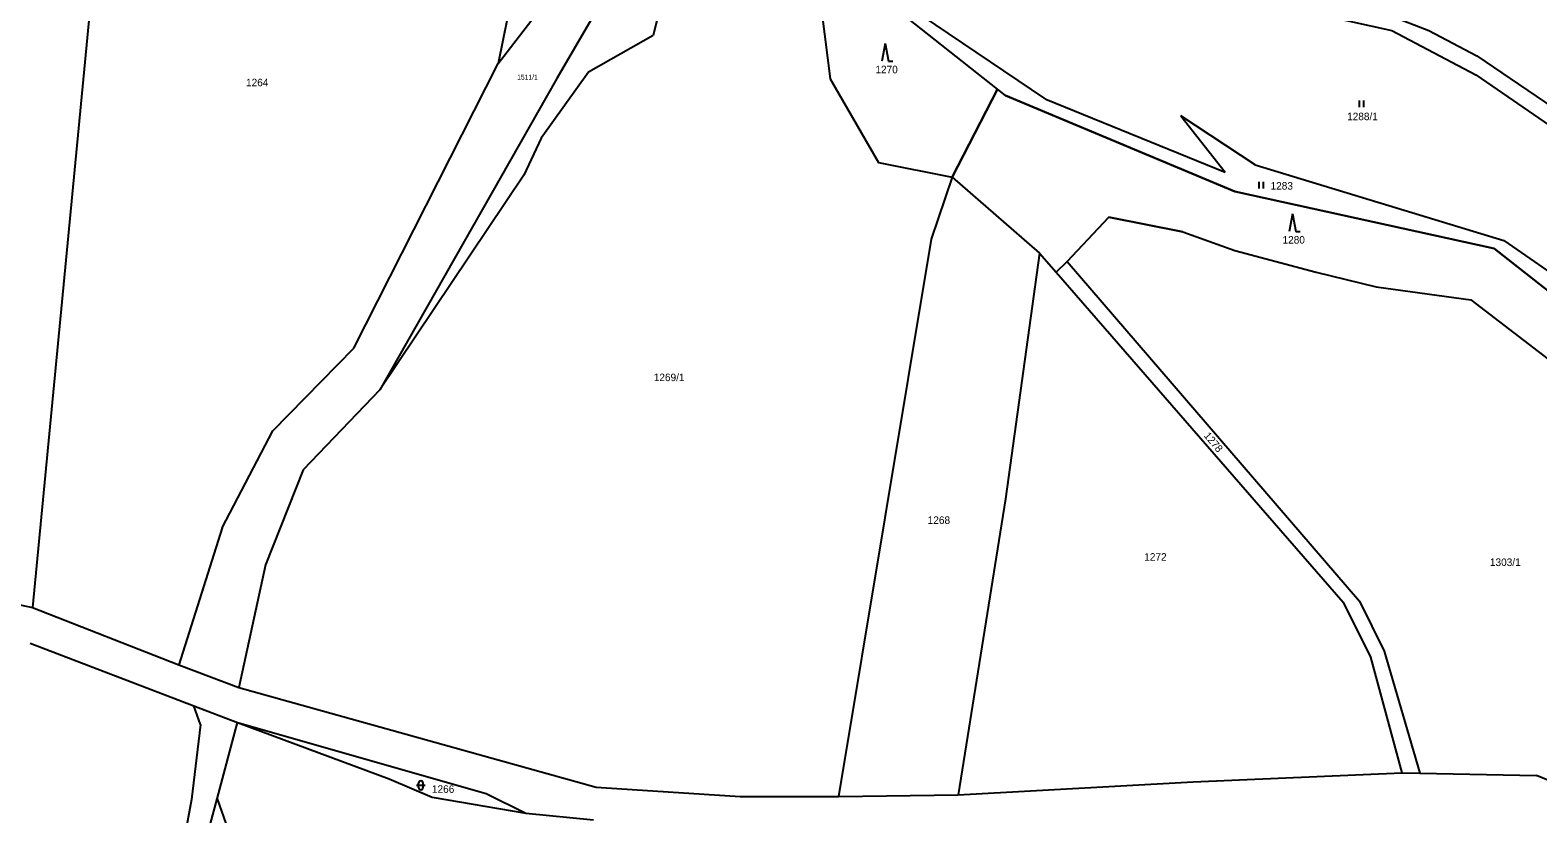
# Model space of a CAD drawing. Extents: x -760642 to -757221, y -1092371 to -1088855.
# Drawn here: x -759213 to -758872.5, y -1091585.2 to -1091408.1 of the extents above; entities that cross this region are included whole.
import ezdxf

# ---------------------------------------------------------------- set-up
doc = ezdxf.new("R2010")
doc.units = 0
for name, color, linetype in [('Vrstva 1', 7, 'Continuous'), ('Vrstva 18', 7, 'Continuous'), ('Vrstva 25', 7, 'Continuous'), ('Vrstva 30', 7, 'Continuous')]:
    doc.layers.add(name, color=color, linetype=linetype)

msp = doc.modelspace()

# ---------------------------------------------------------------- linework, layer by layer
at = {"layer": 'Vrstva 1'}
for p, q in [((-759195.54, -1091362.4), (-759212.45, -1091538.54)), ((-759071.48, -1091380.29), (-759094.05, -1091419.03)), ((-759065.08, -1091379.29), (-759072.26, -1091409.34)), ((-759107.31, -1091415.63), (-759088.88, -1091391.57)), ((-758994.53, -1091421.46), (-759033.32, -1091390.76)), ((-759102.73, -1091393.05), (-759107.31, -1091415.63)), ((-758983.6, -1091423.73), (-759022.6, -1091397.37)), ((-759034.19, -1091404.31), (-759032.3, -1091419.1)), ((-758925.9, -1091403.68), (-758905.47, -1091408.19)), ((-758906.01, -1091404.76), (-758897.1, -1091408.22)), ((-758905.47, -1091408.19), (-758886.45, -1091418.22)), ((-758897.1, -1091408.22), (-758886.25, -1091413.92)), ((-759072.26, -1091409.34), (-759086.89, -1091417.6)), ((-759139.89, -1091479.95), (-759107.31, -1091415.63)), ((-758886.25, -1091413.92), (-758865.29, -1091428.18)), ((-759094.05, -1091419.03), (-759134.03, -1091489.38)), ((-759086.89, -1091417.6), (-759097.55, -1091432.53)), ((-759032.3, -1091419.1), (-759021.37, -1091438)), ((-758886.45, -1091418.22), (-758868.64, -1091430.48)), ((-759004.76, -1091441.33), (-758994.53, -1091421.46)), ((-758992.67, -1091422.93), (-758994.53, -1091421.46)), ((-758992.67, -1091422.93), (-758940.91, -1091444.56)), ((-758983.6, -1091423.73), (-758943.12, -1091440.2)), ((-758953.11, -1091427.52), (-758943.12, -1091440.2)), ((-758936.35, -1091438.54), (-758953.11, -1091427.52)), ((-759097.55, -1091432.53), (-759101.48, -1091440.86)), ((-759021.37, -1091438), (-759004.76, -1091441.33)), ((-758936.35, -1091438.54), (-758880.16, -1091455.67)), ((-759101.48, -1091440.86), (-759134.03, -1091489.38)), ((-759004.76, -1091441.33), (-759009.52, -1091455.35)), ((-759004.76, -1091441.33), (-758985.05, -1091458.48)), ((-758940.91, -1091444.56), (-758882.3, -1091457.47)), ((-758978.8, -1091460.38), (-758969.33, -1091450.37)), ((-758952.63, -1091453.68), (-758969.33, -1091450.37)), ((-759009.52, -1091455.35), (-759030.43, -1091581.29)), ((-758952.63, -1091453.68), (-758940.88, -1091457.9)), ((-758880.16, -1091455.67), (-758833.58, -1091488.02)), ((-758985.05, -1091458.48), (-758992.74, -1091514.02)), ((-758985.05, -1091458.48), (-758981.25, -1091462.8)), ((-758940.88, -1091457.9), (-758922.53, -1091462.8)), ((-758882.3, -1091457.47), (-758836.43, -1091493.56)), ((-758981.25, -1091462.8), (-758978.8, -1091460.38)), ((-758981.25, -1091462.8), (-758916.42, -1091537.37)), ((-758978.8, -1091460.38), (-758912.74, -1091537.13)), ((-758922.53, -1091462.8), (-758908.98, -1091466.1)), ((-758908.98, -1091466.1), (-758887.62, -1091469.02)), ((-758887.62, -1091469.02), (-758865.92, -1091485.73)), ((-759158.16, -1091498.63), (-759139.89, -1091479.95)), ((-759134.03, -1091489.38), (-759151.37, -1091507.47)), ((-759169.64, -1091520.59), (-759158.16, -1091498.63)), ((-759151.37, -1091507.47), (-759159.86, -1091528.89)), ((-759355.96, -1091508.53), (-759212.45, -1091538.54)), ((-758992.74, -1091514.02), (-759003.41, -1091580.89)), ((-759169.64, -1091520.59), (-759179.43, -1091551.52)), ((-759159.86, -1091528.89), (-759165.86, -1091556.61)), ((-758916.42, -1091537.37), (-758910.26, -1091549.78)), ((-758912.74, -1091537.13), (-758907.2, -1091548.45)), ((-759212.45, -1091538.54), (-759179.43, -1091551.52)), ((-759213.03, -1091546.61), (-759176.04, -1091560.8)), ((-758907.2, -1091548.45), (-758899.13, -1091576.01)), ((-759179.43, -1091551.52), (-759165.86, -1091556.61)), ((-758910.26, -1091549.78), (-758903.15, -1091575.93)), ((-759165.86, -1091556.61), (-759085.18, -1091579.14)), ((-759176.04, -1091560.8), (-759166.19, -1091564.54)), ((-759174.51, -1091564.97), (-759176.04, -1091560.8)), ((-759174.51, -1091564.97), (-759176.55, -1091581.93)), ((-759170.74, -1091581.78), (-759166.19, -1091564.54)), ((-759166.19, -1091564.54), (-759110.03, -1091580.58)), ((-759166.19, -1091564.54), (-759131.92, -1091577.28)), ((-759131.92, -1091577.28), (-759122.22, -1091581.41)), ((-759085.18, -1091579.14), (-759052.66, -1091581.28)), ((-759003.41, -1091580.89), (-758950.32, -1091577.95)), ((-758950.32, -1091577.95), (-758903.15, -1091575.93)), ((-758903.15, -1091575.93), (-758899.13, -1091576.01)), ((-758899.13, -1091576.01), (-758872.79, -1091576.55)), ((-758865.61, -1091579.44), (-758872.79, -1091576.55)), ((-759176.55, -1091581.93), (-759178.92, -1091594.54)), ((-759174.11, -1091594.26), (-759170.74, -1091581.78)), ((-759170.74, -1091581.78), (-759166.06, -1091595.03)), ((-759122.22, -1091581.41), (-759101.04, -1091585.03)), ((-759110.03, -1091580.58), (-759101.04, -1091585.03)), ((-759052.66, -1091581.28), (-759030.43, -1091581.29)), ((-759030.43, -1091581.29), (-759003.41, -1091580.89)), ((-759101.04, -1091585.03), (-759085.76, -1091586.53))]:
    msp.add_line(p, q, dxfattribs=at)
at = {"layer": 'Vrstva 25'}
for p, q in [((-759019.872, -1091411.159), (-759020.605, -1091415.159)), ((-759019.872, -1091411.159), (-759019.139, -1091415.159)), ((-759019.139, -1091415.159), (-759018.139, -1091415.159)), ((-758912.827, -1091424.035), (-758912.827, -1091425.535)), ((-758911.805, -1091425.535), (-758911.805, -1091424.035)), ((-758935.457, -1091442.415), (-758935.457, -1091443.915)), ((-758934.435, -1091443.915), (-758934.435, -1091442.415)), ((-758927.872, -1091449.639), (-758928.605, -1091453.639)), ((-758927.872, -1091449.639), (-758927.139, -1091453.639)), ((-758927.139, -1091453.639), (-758926.139, -1091453.639)), ((-759125.77, -1091578.72), (-759123.77, -1091578.72)), ((-759125.27, -1091579.22), (-759125.27, -1091578.22)), ((-759124.27, -1091579.22), (-759124.27, -1091578.22))]:
    msp.add_line(p, q, dxfattribs=at)
for centre, start, end in [((-759124.77, -1091578.22), 0, 180), ((-759124.77, -1091579.22), 180, 0)]:
    msp.add_arc(centre, 0.5, start, end, dxfattribs=at)
at = {"layer": 'Vrstva 30'}
for points in [[(-759004.76, -1091441.33), (-758994.53, -1091421.46), (-759033.32, -1091390.76), (-759070.89, -1091367.57), (-759065.08, -1091379.29), (-759049.93, -1091387.73), (-759034.19, -1091404.31), (-759032.3, -1091419.1), (-759021.37, -1091438), (-759004.76, -1091441.33)], [(-759004.76, -1091441.33), (-758985.05, -1091458.48), (-758981.25, -1091462.8), (-758978.8, -1091460.38), (-758969.33, -1091450.37), (-758952.63, -1091453.68), (-758940.88, -1091457.9), (-758922.53, -1091462.8), (-758908.98, -1091466.1), (-758887.62, -1091469.02), (-758865.92, -1091485.73), (-758847.93, -1091504.47), (-758837.06, -1091508.57), (-758835.49, -1091508.97), (-758831.8, -1091496.02), (-758836.43, -1091493.56), (-758882.3, -1091457.47), (-758940.91, -1091444.56), (-758992.67, -1091422.93), (-758994.53, -1091421.46), (-759004.76, -1091441.33)]]:
    msp.add_lwpolyline(points, dxfattribs=at)

# ---------------------------------------------------------------- texts
at = {"layer": 'Vrstva 18'}
for s, height, p in [('1264', 1.7, (-759164.25, -1091420.81)), ('1511/1', 1.1, (-759102.998, -1091419.3)), ('1270', 1.7, (-759022.09, -1091417.87)), ('1288/1', 1.7, (-758915.55, -1091428.47)), ('1283', 1.7, (-758932.84, -1091444.15)), ('1280', 1.7, (-758930.138, -1091456.35)), ('1269/1', 1.7, (-759072.15, -1091487.42)), ('1268', 1.7, (-759010.28, -1091519.68)), ('1272', 1.7, (-758961.37, -1091527.99)), ('1303/1', 1.7, (-758883.29, -1091529.18)), ('1266', 1.7, (-759122.26, -1091580.43))]:
    msp.add_text(s, height=height, dxfattribs=at).set_placement(p)
msp.add_text('1278', height=1.7, rotation=309.9159, dxfattribs=at).set_placement((-758948.01, -1091499.8))

doc.saveas('drawing.dxf')
